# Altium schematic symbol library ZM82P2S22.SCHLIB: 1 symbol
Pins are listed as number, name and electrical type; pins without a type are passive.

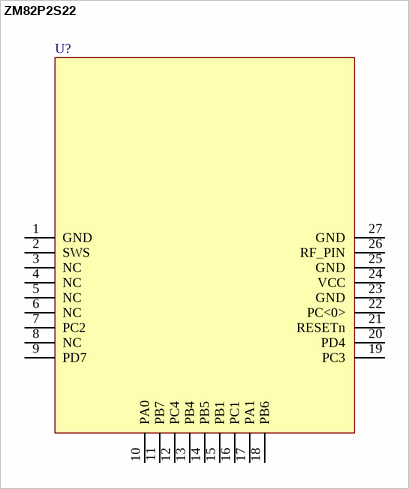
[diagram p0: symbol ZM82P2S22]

## ZM82P2S22
designator U?
ZM82P2S22 Module,ZLGLIB
pins: 1 GND, 2 SWS, 3 NC, 4 NC, 5 NC, 6 NC, 7 PC2, 8 NC, 9 PD7, 10 PA0, 11 PB7, 12 PC4, 13 PB4, 14 PB5, 15 PB1, 16 PC1, 17 PA1, 18 PB6, 19 PC3, 20 PD4, 21 RESETn, 22 PC<0>, 23 GND, 24 VCC, 25 GND, 26 RF_PIN, 27 GND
